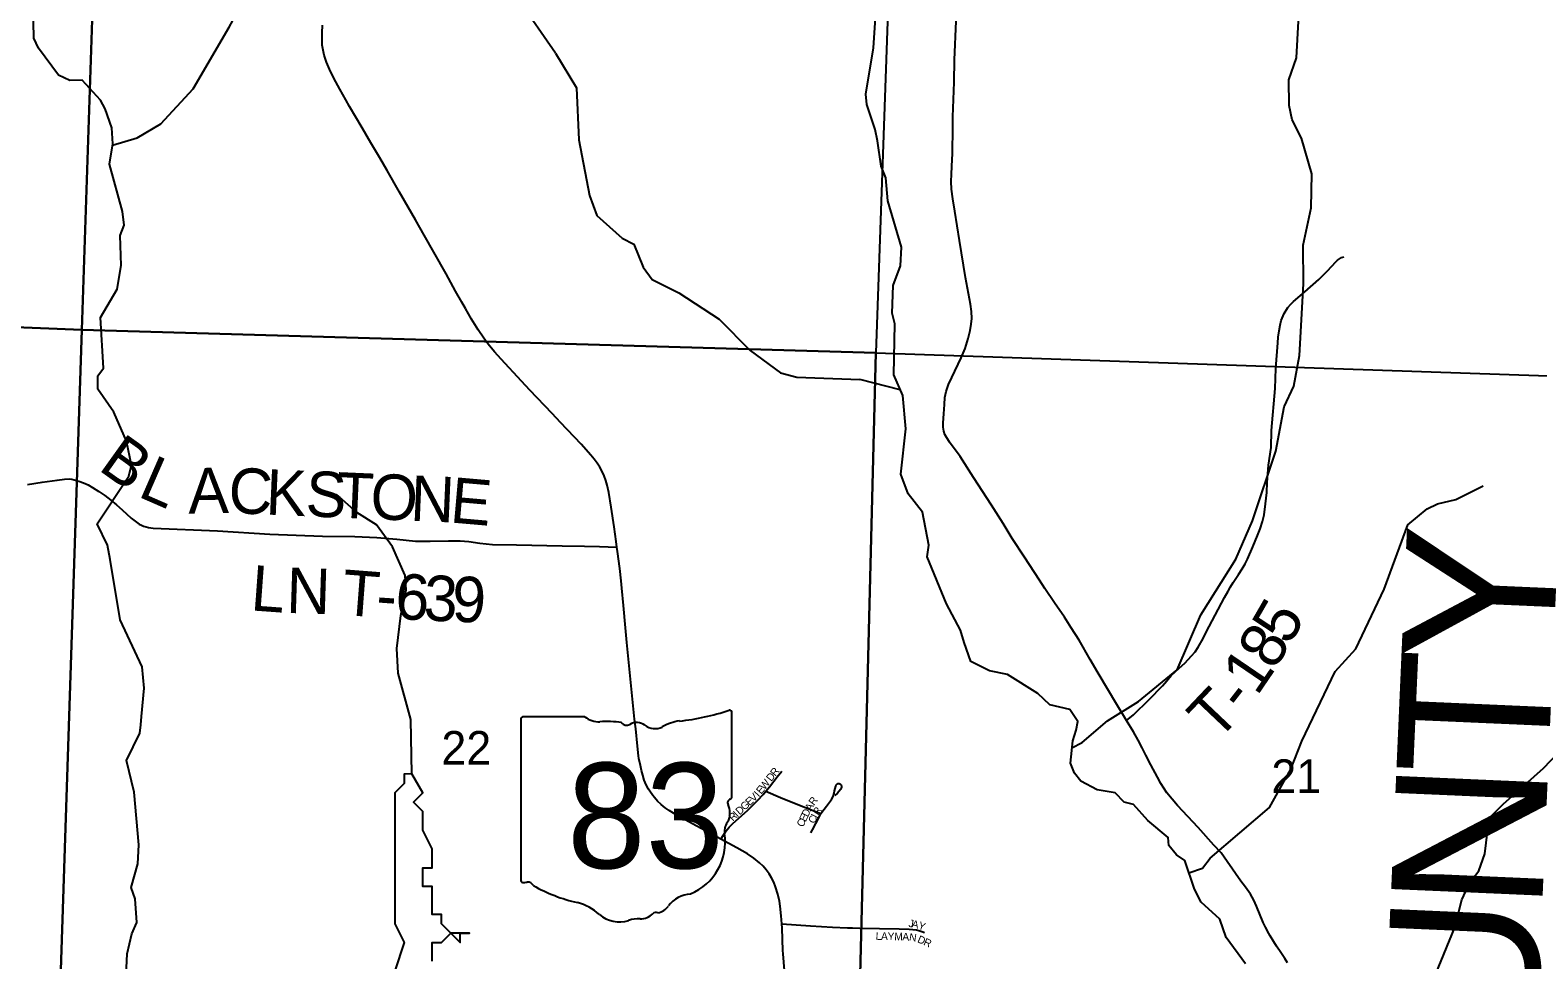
# Model space of a CAD drawing. Extents: x 0 to 34, y 0 to 22.
# Drawn here: x 26.645 to 28.529, y 18.518 to 19.68 of the extents above; entities that cross this region are included whole.
import ezdxf

# ---------------------------------------------------------------- set-up
doc = ezdxf.new("R2010")
doc.units = 0
for name, color, linetype in [('GM_X_Adjacent_County_Text', 7, 'Continuous'), ('GM_X_County_Road', 7, 'Continuous'), ('GM_X_Minor_Lake', 7, 'Continuous'), ('GM_X_Minor_River', 7, 'Continuous'), ('GM_X_Section', 7, 'Continuous'), ('GM_X_Section_Text', 7, 'Continuous'), ('GM_X_State_Location', 7, 'Continuous'), ('GM_X_State_Route', 7, 'Continuous'), ('GM_X_State_Shield', 7, 'Continuous'), ('GM_X_Township_Road', 7, 'Continuous'), ('GM_X_Township_Road_Text', 7, 'Continuous'), ('GM_X_Township_Subdivision', 7, 'Continuous'), ('GM_X_Township_Subdivision_Text', 7, 'Continuous')]:
    doc.layers.add(name, color=color, linetype=linetype)

msp = doc.modelspace()

# ---------------------------------------------------------------- linework, layer by layer
at = {"layer": 'GM_X_County_Road'}
for points in [[(28.0154, 18.8171), (28.0034, 18.8368), (27.9801, 18.8762), (27.9701, 18.8932), (27.9562, 18.9172), (27.9464, 18.933), (27.9378, 18.946), (27.9255, 18.9639), (27.9133, 18.9819), (27.9065, 18.9923), (27.8879, 19.021), (27.8727, 19.0445), (27.8613, 19.063), (27.8469, 19.086), (27.8244, 19.1206), (27.8075, 19.1467), (27.7943, 19.165), (27.7886, 19.1744), (27.787, 19.1785), (27.7865, 19.1836), (27.7865, 19.189), (27.787, 19.2003), (27.7878, 19.2119), (27.7886, 19.2206), (27.79, 19.2281), (27.7929, 19.237), (27.797, 19.2456), (27.8088, 19.2702), (27.814, 19.282), (27.8176, 19.2942), (27.8202, 19.3042), (27.8215, 19.3123), (27.8223, 19.3193), (27.8218, 19.3282), (27.8205, 19.3371), (27.8144, 19.3707), (27.8119, 19.3861), (27.8068, 19.4167), (27.8037, 19.4351), (27.8007, 19.4535), (27.7984, 19.4688), (27.7969, 19.4811), (27.7964, 19.4904), (27.7967, 19.4997), (27.7977, 19.5183), (27.7978, 19.5245), (27.7982, 19.5587), (27.7985, 19.5712), (27.7994, 19.5929), (27.8001, 19.6146), (27.8003, 19.6426), (27.8026, 19.6909)], [(28.2164, 18.5143), (28.2131, 18.5195), (28.2098, 18.5247), (28.2081, 18.5273), (28.203, 18.5351), (28.1997, 18.5403), (28.1949, 18.548), (28.1934, 18.5507), (28.189, 18.5588), (28.1863, 18.5645), (28.1778, 18.5849), (28.1745, 18.5924), (28.1705, 18.6), (28.1643, 18.6086), (28.1584, 18.6162), (28.1414, 18.6407), (28.1335, 18.6515), (28.1247, 18.6612), (28.105, 18.6833), (28.0791, 18.7106), (28.0656, 18.7265), (28.0583, 18.7384), (28.054, 18.7464), (28.0459, 18.7615), (28.0397, 18.7737), (28.0351, 18.7828), (28.03, 18.7926), (28.0241, 18.8028), (28.0154, 18.8171)]]:
    msp.add_lwpolyline(points, dxfattribs=at)
at = {"layer": 'GM_X_Minor_Lake'}
for points in [[(27.1224, 18.7502), (27.1127, 18.7501), (27.1127, 18.7384), (27.101, 18.7267), (27.101, 18.715), (27.101, 18.6799), (27.101, 18.6682), (27.101, 18.6448), (27.101, 18.6214), (27.101, 18.6097), (27.101, 18.5863), (27.101, 18.5629), (27.1127, 18.5395), (27.1009, 18.5044), (27.0892, 18.481), (27.0775, 18.4693), (27.0775, 18.4459), (27.0775, 18.4225), (27.0775, 18.3873), (27.0658, 18.3522), (27.0895, 18.3374)], [(27.1477, 18.5161), (27.1478, 18.5395), (27.1595, 18.5395), (27.1712, 18.5512), (27.1829, 18.5395), (27.1829, 18.5512), (27.1946, 18.5512), (27.1829, 18.5512), (27.1712, 18.5512), (27.1595, 18.5629), (27.1595, 18.5746), (27.1478, 18.5746), (27.1478, 18.5863), (27.1478, 18.6097), (27.1361, 18.6097), (27.1361, 18.6331), (27.1478, 18.6331), (27.1478, 18.6565), (27.1361, 18.6799), (27.1361, 18.6916), (27.1361, 18.7033), (27.1244, 18.715), (27.1361, 18.7267), (27.1224, 18.7502)]]:
    msp.add_lwpolyline(points, dxfattribs=at)
at = {"layer": 'GM_X_Minor_River'}
for points in [[(26.7483, 19.5359), (26.7793, 19.5451), (26.8087, 19.5624), (26.849, 19.6062), (26.8941, 19.6835), (26.9124, 19.7169), (26.9225, 19.7489), (26.924, 19.8141), (26.9291, 19.8619), (26.9254, 19.9006), (26.9174, 19.9779), (26.9124, 19.9991), (26.904, 20.0135)], [(27.302, 19.6509), (27.2557, 19.7178), (27.2438, 19.7587)], [(28.1641, 18.5128), (28.1399, 18.5459), (28.1321, 18.5689), (28.1088, 18.5899), (28.1003, 18.6061), (28.0882, 18.642), (28.0779, 18.6491), (28.0683, 18.6607), (28.0675, 18.671), (28.0419, 18.6919), (28.0243, 18.7122), (28.0125, 18.7151), (28.0011, 18.7267), (27.9787, 18.7303), (27.9585, 18.7414), (27.9505, 18.7512), (27.9454, 18.7637), (27.9482, 18.7914), (27.9526, 18.8051), (27.9547, 18.8157), (27.9447, 18.8308), (27.9197, 18.8366), (27.9048, 18.8508), (27.8667, 18.8743), (27.8443, 18.879), (27.8208, 18.8908), (27.8126, 18.9143), (27.8079, 18.9297), (27.7905, 18.9629), (27.7664, 19.0214), (27.7685, 19.0362), (27.7605, 19.0775), (27.7425, 19.1004), (27.7335, 19.125), (27.7397, 19.1815), (27.7359, 19.2232), (27.7246, 19.2488), (27.7259, 19.3125), (27.7227, 19.3262), (27.7238, 19.3607), (27.733, 19.385), (27.7343, 19.4085), (27.717, 19.4664), (27.7145, 19.4952), (27.709, 19.5095), (27.7041, 19.5413), (27.7013, 19.5553), (27.6908, 19.5866), (27.6895, 19.5995), (27.6991, 19.6576), (27.7044, 19.7331)], [(26.7654, 18.499), (26.7668, 18.5255), (26.7723, 18.5506), (26.7787, 18.5647), (26.7766, 18.5942), (26.7716, 18.6082), (26.7801, 18.6379), (26.7811, 18.6618), (26.7755, 18.7274), (26.7658, 18.7671), (26.7823, 18.801), (26.7837, 18.8116), (26.7844, 18.8219), (26.788, 18.8575), (26.7852, 18.8841), (26.758, 18.9427), (26.7454, 19.0181), (26.7419, 19.0359), (26.7293, 19.0628), (26.7687, 19.1222), (26.7721, 19.1362), (26.7658, 19.1661), (26.7501, 19.2025), (26.7299, 19.2312), (26.7301, 19.2479), (26.7369, 19.2574), (26.7335, 19.3207), (26.7542, 19.3561), (26.7593, 19.3857), (26.758, 19.4229), (26.7628, 19.4358), (26.7608, 19.4529), (26.7446, 19.5123), (26.7486, 19.5377), (26.7474, 19.5575), (26.7393, 19.5813), (26.7335, 19.5923), (26.7103, 19.6172), (26.6951, 19.6167), (26.6807, 19.6235), (26.6559, 19.6571), (26.6501, 19.6696), (26.6491, 19.7101)], [(27.9473, 18.7828), (27.9599, 18.7896), (27.9918, 18.8165), (28.0305, 18.8408), (28.0789, 18.8804), (28.1084, 18.9489), (28.1519, 19.0188), (28.173, 19.0664), (28.2019, 19.1535), (28.2123, 19.209), (28.2245, 19.2349), (28.2317, 19.2729), (28.2364, 19.3628), (28.2363, 19.4109), (28.246, 19.4577), (28.247, 19.5001), (28.2341, 19.5447), (28.2225, 19.5674), (28.2185, 19.5855), (28.2182, 19.6174), (28.2277, 19.6451), (28.2302, 19.691)], [(27.302, 19.6509), (27.3282, 19.6074), (27.3311, 19.5426), (27.3444, 19.473), (27.3537, 19.448), (27.385, 19.4199), (27.3999, 19.4121), (27.4115, 19.3835), (27.4226, 19.368), (27.4561, 19.3513), (27.5064, 19.3185), (27.545, 19.2795), (27.5831, 19.2515), (27.6036, 19.246), (27.6823, 19.2431)], [(27.7327, 19.2304), (27.6823, 19.2431)], [(28.0934, 18.6267), (28.1102, 18.6324), (28.1199, 18.645), (28.1942, 18.7083), (28.2209, 18.7564), (28.2345, 18.7911), (28.2763, 18.8783), (28.3018, 18.9067), (28.3373, 18.981), (28.3671, 19.0617), (28.3911, 19.0816), (28.4039, 19.0878), (28.4269, 19.093), (28.4611, 19.1101)], [(27.1224, 18.7502), (27.1213, 18.8181), (27.1051, 18.876), (27.1038, 18.9071), (27.1088, 18.9481), (27.1151, 18.9804), (27.1139, 18.9982), (27.0981, 19.0342), (27.0783, 19.0617), (27.0536, 19.0768), (27.0284, 19.0994)], [(28.2814, 18.3155), (28.2838, 18.3207), (28.3576, 18.3894), (28.4018, 18.5006), (28.4258, 18.5584), (28.4345, 18.593), (28.4445, 18.6144), (28.4557, 18.6293), (28.463, 18.6506), (28.4686, 18.695), (28.4862, 18.7123), (28.5364, 18.7575), (28.5723, 18.7951), (28.5883, 18.8222), (28.6174, 18.8615), (28.6302, 18.8984), (28.6331, 18.9106), (28.6375, 18.9247)]]:
    msp.add_lwpolyline(points, dxfattribs=at)
at = {"layer": 'GM_X_Section'}
for points in [[(25.7533, 20.3558), (26.7437, 20.3179), (26.7101, 19.3051), (25.7174, 19.3453)], [(26.7437, 20.3179), (27.7374, 20.2821), (27.7021, 19.2764), (26.7101, 19.3051)], [(25.7174, 19.3453), (26.7101, 19.3051), (26.6775, 18.3147), (25.6829, 18.3575)], [(27.7021, 19.2764), (27.6773, 18.2845), (26.6775, 18.3147), (26.7101, 19.3051)], [(28.7005, 19.2422), (28.6651, 18.2435), (27.6773, 18.2845), (27.7021, 19.2764)]]:
    msp.add_lwpolyline(points, close=True, dxfattribs=at)
at = {"layer": 'GM_X_State_Route'}
for points in [[(27.5864, 18.5253), (27.5861, 18.5295), (27.5851, 18.5574), (27.5847, 18.563), (27.584, 18.5729), (27.5828, 18.5852), (27.5818, 18.5913), (27.5797, 18.6002), (27.5769, 18.609), (27.5746, 18.6148), (27.5719, 18.6203), (27.5688, 18.6255), (27.5652, 18.6305), (27.5612, 18.6351), (27.5567, 18.6393), (27.5496, 18.6451), (27.5419, 18.6503), (27.5286, 18.6581), (27.5086, 18.6688), (27.504, 18.6713), (27.4683, 18.6902), (27.4547, 18.6978), (27.4441, 18.7044), (27.439, 18.708), (27.4341, 18.7119), (27.4295, 18.7163), (27.4254, 18.721), (27.4235, 18.7235), (27.4198, 18.7286), (27.4181, 18.7312), (27.4152, 18.7368), (27.4128, 18.7426), (27.4108, 18.7485), (27.4092, 18.7546), (27.4079, 18.7606), (27.4061, 18.7697), (27.4056, 18.7728), (27.4044, 18.7851), (27.4021, 18.8065), (27.4006, 18.8188), (27.391, 18.9143), (27.3894, 18.9329), (27.3869, 18.9607), (27.3849, 18.9823), (27.3839, 18.9915), (27.3821, 19.0069), (27.3794, 19.0283), (27.3787, 19.0334), (27.3777, 19.0406), (27.375, 19.059), (27.3716, 19.0837), (27.3686, 19.102), (27.3666, 19.111), (27.3648, 19.1169), (27.3627, 19.1227), (27.3601, 19.1282), (27.3571, 19.1336), (27.3538, 19.1387), (27.3501, 19.1436), (27.3462, 19.1484), (27.3338, 19.1622), (27.3083, 19.1893), (27.2977, 19.2007), (27.2699, 19.2299), (27.2592, 19.2412), (27.2339, 19.2685), (27.2257, 19.2778), (27.2178, 19.2874), (27.2122, 19.2949), (27.2052, 19.3052), (27.1971, 19.3184), (27.1893, 19.3318), (27.1847, 19.3399), (27.1771, 19.3534), (27.1651, 19.3751), (27.15, 19.4021), (27.1377, 19.4236), (27.1269, 19.4425), (27.1222, 19.4505), (27.1176, 19.4585), (27.1069, 19.4773), (27.0915, 19.5041), (27.0822, 19.5202), (27.0713, 19.539), (27.0603, 19.5577), (27.0445, 19.5843), (27.0398, 19.5924), (27.0322, 19.6059), (27.0249, 19.6196), (27.0195, 19.6308), (27.0159, 19.6395), (27.0129, 19.6484), (27.0115, 19.6545), (27.0105, 19.6607), (27.0101, 19.667), (27.0102, 19.6764), (27.0109, 19.6857)], [(27.5935, 18.4158), (27.5921, 18.4367), (27.5892, 18.4831), (27.5884, 18.4956), (27.5879, 18.5048), (27.5864, 18.5253)]]:
    msp.add_lwpolyline(points, dxfattribs=at)
at = {"layer": 'GM_X_State_Shield'}
for p, q in [((27.3384, 18.8217), (27.2611, 18.8217)), ((27.5222, 18.722), (27.5222, 18.8267)), ((27.2585, 18.8183), (27.2585, 18.6181)), ((27.5222, 18.722), (27.5222, 18.722))]:
    msp.add_line(p, q, dxfattribs=at)
for centre, radius, start, end in [((27.2616, 18.8187), 0.00305, 98.1301, 188.1301), ((27.3568, 18.8449), 0.0296, 231.6195, 271.1119), ((27.4283, 19.0945), 0.2796, 275.8445, 288.9065), ((27.5193, 18.8271), 0.00294, 351.8621, 97.738), ((27.3666, 18.7094), 0.1064, 80.4867, 94.9883), ((27.3907, 18.8197), 0.00855, 219.7921, 297.1024), ((27.4033, 18.7966), 0.0178, 54.4667, 119.1411), ((27.4262, 18.8283), 0.0214, 233.8562, 294.8282), ((27.464, 18.7606), 0.0563, 97.3462, 120.7689), ((27.5215, 18.7143), 0.00454, 107.944, 210.337), ((27.4926, 18.7011), 0.0273, 340.033, 23.6496), ((27.5191, 18.7216), 0.00314, 289.6038, 7.7341), ((27.5327, 18.6782), 0.0198, 136.8065, 186.9296), ((27.444, 18.6649), 0.0699, 292.3089, 8.9858), ((27.2616, 18.6177), 0.00308, 171.9584, 258.3066), ((27.2621, 18.6382), 0.0235, 267.339, 280.6039), ((27.2669, 18.6066), 0.00848, 29.7484, 93.2717), ((27.3739, 18.7864), 0.2019, 240.4129, 257.1985), ((27.4734, 18.562), 0.0383, 94.4031, 142.5768), ((27.3137, 18.5282), 0.0632, 47.1842, 75.836), ((27.4275, 18.5712), 0.00601, 65.7517, 132.6484), ((27.4249, 18.5987), 0.0226, 282.8732, 323.2771), ((27.3821, 18.6056), 0.0401, 230.7004, 286.2918), ((27.4052, 18.5364), 0.0329, 85.6951, 111.2099), ((27.4082, 18.5906), 0.0214, 268.777, 315.5493)]:
    msp.add_arc(centre, radius, start, end, dxfattribs=at)
at = {"layer": 'GM_X_Township_Road'}
for points in [[(28.0154, 18.8171), (28.0243, 18.8241), (28.0439, 18.8432), (28.0606, 18.8605), (28.066, 18.8667), (28.0714, 18.8732), (28.0814, 18.8826), (28.0882, 18.8888), (28.0968, 18.8977), (28.1011, 18.9028), (28.1051, 18.9088), (28.1111, 18.9196), (28.1151, 18.9274), (28.1264, 18.9488), (28.138, 18.9707), (28.1425, 18.9788), (28.1455, 18.9842), (28.1487, 18.9894), (28.1554, 18.9996), (28.1599, 19.0064), (28.1637, 19.0129), (28.1666, 19.0188), (28.1734, 19.0342), (28.179, 19.0482), (28.1823, 19.0566), (28.1855, 19.0657), (28.1874, 19.0741), (28.1893, 19.0876), (28.1906, 19.1021), (28.1912, 19.1143), (28.1927, 19.1359), (28.196, 19.158), (28.1968, 19.1795), (28.2012, 19.2319), (28.2022, 19.2567), (28.2046, 19.2889), (28.2049, 19.296), (28.2061, 19.304), (28.2074, 19.3109), (28.2087, 19.3169), (28.2123, 19.3256), (28.2171, 19.3332), (28.2206, 19.3371), (28.2241, 19.3404), (28.2384, 19.3527), (28.2556, 19.368), (28.2601, 19.3721), (28.2666, 19.3787), (28.277, 19.39), (28.2792, 19.3921), (28.2815, 19.394), (28.2841, 19.3957), (28.287, 19.3965)], [(26.6422, 19.1118), (26.6605, 19.1149), (26.679, 19.1175), (26.6882, 19.1185), (26.6944, 19.1188), (26.6975, 19.1185), (26.7005, 19.1179), (26.7064, 19.1161), (26.7122, 19.1139), (26.7178, 19.1113), (26.7232, 19.1083), (26.7311, 19.1033), (26.7388, 19.098), (26.7462, 19.0924), (26.7534, 19.0865), (26.7604, 19.0803), (26.7717, 19.0697), (26.7765, 19.0659), (26.7816, 19.0625), (26.7844, 19.061), (26.7872, 19.0599), (26.7902, 19.059), (26.7932, 19.0583), (26.7993, 19.0573), (26.8794, 19.0541), (26.9448, 19.0499), (27.0109, 19.0475), (27.0513, 19.0468), (27.0788, 19.0458), (27.1036, 19.0436), (27.1268, 19.0411), (27.1452, 19.0412), (27.168, 19.0416), (27.1828, 19.0417), (27.1936, 19.0407), (27.2073, 19.0387), (27.2231, 19.037), (27.2533, 19.0366), (27.3103, 19.0351), (27.3382, 19.035), (27.3568, 19.0345), (27.3787, 19.0334)]]:
    msp.add_lwpolyline(points, dxfattribs=at)
at = {"layer": 'GM_X_Township_Subdivision'}
for points in [[(27.5647, 18.7286), (27.5693, 18.7343), (27.5788, 18.7467), (27.5848, 18.7538)], [(27.5086, 18.6688), (27.515, 18.6791), (27.519, 18.6838), (27.5234, 18.6881), (27.542, 18.7047), (27.5553, 18.7178), (27.5615, 18.7247), (27.5647, 18.7286)], [(27.5647, 18.7286), (27.5829, 18.7207), (27.6027, 18.713), (27.6141, 18.7085), (27.6335, 18.7008)], [(27.6335, 18.7008), (27.6374, 18.7063), (27.6405, 18.7101), (27.6467, 18.7182), (27.6484, 18.7211), (27.6494, 18.7234), (27.65, 18.7262), (27.6507, 18.7291), (27.6521, 18.7351), (27.6528, 18.7365), (27.6537, 18.7376), (27.6551, 18.7383), (27.6564, 18.7382), (27.6579, 18.7375), (27.6587, 18.7366), (27.6592, 18.735), (27.6592, 18.7336), (27.6588, 18.7324), (27.658, 18.7308), (27.6541, 18.7262), (27.6509, 18.7231)], [(27.6211, 18.6765), (27.6229, 18.6804), (27.6271, 18.6881), (27.6316, 18.6971), (27.6335, 18.7008)], [(27.5847, 18.563), (27.6204, 18.5606), (27.6482, 18.5588), (27.6667, 18.5581), (27.6729, 18.5578), (27.682, 18.5575), (27.7068, 18.5569), (27.7315, 18.5566), (27.7438, 18.5563), (27.7483, 18.556), (27.7528, 18.5555), (27.756, 18.5546), (27.7597, 18.5535), (27.7629, 18.5521)]]:
    msp.add_lwpolyline(points, dxfattribs=at)

# ---------------------------------------------------------------- texts
at = {"layer": 'GM_X_Adjacent_County_Text'}
for s, p in [('Y', (28.548, 18.8862)), ('T', (28.5418, 18.7447)), ('N', (28.5345, 18.5774)), ('U', (28.5271, 18.41))]:
    msp.add_text(s, height=0.1894, rotation=87.496, dxfattribs=at).set_placement(p)
at = {"layer": 'GM_X_Section_Text'}
for s, p in [('22', (27.1593, 18.762)), ('21', (28.1964, 18.7266))]:
    msp.add_text(s, height=0.04186, rotation=0, dxfattribs=at).set_placement(p)
at = {"layer": 'GM_X_State_Location'}
msp.add_text('83', height=0.000189, rotation=0, dxfattribs=at).set_placement((27.3397, 18.6911))
for s in ['s', 'r']:
    msp.add_text(s, height=0.000189, dxfattribs=at).set_placement((27.3874, 18.7049))
at = {"layer": 'GM_X_State_Shield'}
msp.add_text('83', height=0.13184, dxfattribs=at).set_placement((27.3163, 18.6323))
at = {"layer": 'GM_X_Township_Road_Text'}
for s, rotation, p in [('B', 324.4728, (26.7291, 19.1311)), ('L', 336.4183, (26.7784, 19.0976)), ('A', 1.0833, (26.8433, 19.0755)), ('C', 357.5598, (26.8924, 19.0764)), ('K', 357.5622, (26.939, 19.0744)), ('S', 357.5618, (26.9889, 19.0723)), ('T', 357.5609, (27.0272, 19.0707)), ('O', 357.5586, (27.0697, 19.0689)), ('N', 357.5294, (27.1197, 19.0667)), ('E', 355.0399, (27.169, 19.0646)), ('L', 355.8521, (26.92, 18.9547)), ('N', 358.1664, (26.9649, 18.9515)), ('T', 355.6072, (27.0338, 18.9492)), ('6', 356.7361, (27.1006, 18.9442)), ('3', 357.4351, (27.1363, 18.9422)), ('9', 357.9166, (27.1718, 18.9406)), ('-', 356.0436, (27.0766, 18.9459)), ('5', 60.004, (28.2186, 18.9094)), ('8', 59.0994, (28.2001, 18.8785)), ('1', 55.7427, (28.1784, 18.8465)), ('T', 46.5154, (28.1286, 18.7895)), ('-', 52.2267, (28.1619, 18.825))]:
    msp.add_text(s, height=0.0568, rotation=rotation, dxfattribs=at).set_placement(p)
at = {"layer": 'GM_X_Township_Subdivision_Text'}
for s, rotation, p in [('D', 52.0023, (27.5716, 18.7401)), ('R', 51.9817, (27.5767, 18.7466)), ('I', 48.5676, (27.5559, 18.7209)), ('E', 50.1855, (27.5589, 18.7242)), ('W', 51.6818, (27.5633, 18.7295)), ('D', 42.7897, (27.5321, 18.6984)), ('G', 42.7736, (27.5382, 18.7041)), ('E', 42.7588, (27.5444, 18.7098)), ('V', 44.3462, (27.5495, 18.7145)), ('A', 59.9623, (27.6209, 18.7031)), ('R', 53.5477, (27.6249, 18.7101)), ('R', 57.6033, (27.6305, 18.6976)), ('R', 42.767, (27.5235, 18.6905)), ('I', 42.8386, (27.5291, 18.6956)), ('C', 64.2171, (27.6112, 18.683)), ('E', 64.2171, (27.6144, 18.6897)), ('D', 64.2211, (27.6173, 18.6957)), ('C', 64.7162, (27.6256, 18.6874)), ('I', 62.9461, (27.6288, 18.6941)), ('J', 350.5521, (27.7425, 18.5593)), ('A', 348.8701, (27.7465, 18.5586)), ('Y', 341.1988, (27.7543, 18.5571)), ('L', 358.8521, (27.7019, 18.543)), ('A', 358.8668, (27.7086, 18.5429)), ('Y', 358.8668, (27.7169, 18.5427)), ('M', 358.7428, (27.7252, 18.5425)), ('A', 357.9016, (27.7352, 18.5423)), ('N', 351.6875, (27.7433, 18.542)), ('D', 336.7985, (27.7533, 18.5402)), ('R', 336.0424, (27.7609, 18.5369))]:
    msp.add_text(s, height=0.00947, rotation=rotation, dxfattribs=at).set_placement(p)

doc.saveas('drawing.dxf')
